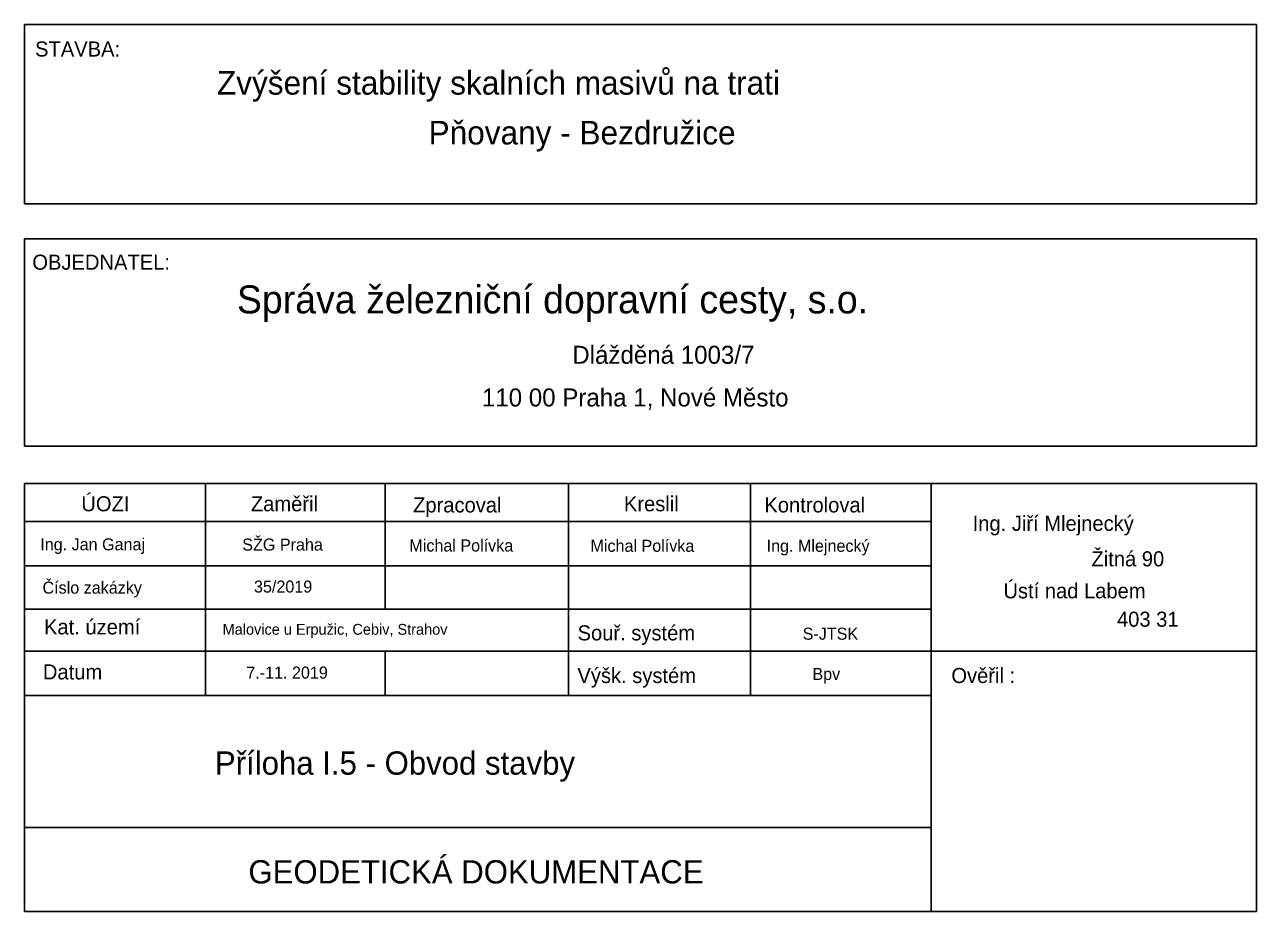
# Model space of a CAD drawing. Extents: x -879530 to -879371, y -1019242 to -1019127.
import ezdxf

# ---------------------------------------------------------------- set-up
doc = ezdxf.new("R2010")
doc.units = 0
doc.layers.add('LEGENDA', color=7, linetype='Continuous')
doc.layers.add('tabulka', color=7, linetype='Continuous')

msp = doc.modelspace()

# ---------------------------------------------------------------- linework, layer by layer
at = {"layer": 'tabulka'}
for p, q in [((-879530.09, -1019186.45), (-879371.44, -1019186.45)), ((-879506.8, -1019186.45), (-879506.8, -1019213.77)), ((-879483.66, -1019186.45), (-879483.66, -1019202.65)), ((-879460.06, -1019186.45), (-879460.06, -1019213.77)), ((-879436.61, -1019186.45), (-879436.61, -1019213.77)), ((-879413.31, -1019241.58), (-879413.31, -1019186.45)), ((-879530.09, -1019191.36), (-879413.31, -1019191.36)), ((-879530.09, -1019197.07), (-879413.31, -1019197.07)), ((-879530.09, -1019202.65), (-879413.31, -1019202.65)), ((-879530.09, -1019208.07), (-879371.44, -1019208.07)), ((-879483.66, -1019208.07), (-879483.66, -1019213.77)), ((-879530.09, -1019213.77), (-879413.31, -1019213.77)), ((-879530.09, -1019230.76), (-879413.31, -1019230.76))]:
    msp.add_line(p, q, dxfattribs=at)
for points in [[(-879530.09, -1019127.36), (-879371.44, -1019127.36), (-879371.44, -1019150.43), (-879530.09, -1019150.43)], [(-879530.09, -1019154.95), (-879371.44, -1019154.95), (-879371.44, -1019181.64), (-879530.09, -1019181.64)]]:
    msp.add_lwpolyline(points, close=True, dxfattribs=at)
msp.add_lwpolyline([(-879371.44, -1019186.45), (-879371.44, -1019241.58), (-879530.09, -1019241.58), (-879530.09, -1019186.45)], dxfattribs=at)

# ---------------------------------------------------------------- texts
at = {"layer": 'LEGENDA'}
for s, p in [('Zvýšení stability skalních masivů na trati', (-879505.32, -1019136.38)), ('Pňovany - Bezdružice', (-879478.06, -1019142.8))]:
    msp.add_text(s, height=3.04, dxfattribs=at).set_placement(p)
at = {"layer": 'tabulka'}
for s, height, p in [('STAVBA:', 1.94, (-879528.75, -1019131.47)), ('OBJEDNATEL:', 1.94, (-879529.1, -1019158.93)), ('Správa železniční dopravní cesty, s.o.', 3.61, (-879502.75, -1019164.56)), ('Dlážděná 1003/7', 2.32, (-879459.55, -1019171.05)), ('110 00 Praha 1, Nové Město', 2.32, (-879471.19, -1019176.55)), ('ÚOZI', 1.94, (-879522.79, -1019190.05)), ('Zaměřil', 1.94, (-879500.95, -1019190.05)), ('Zpracoval', 1.94, (-879480.06, -1019190.2)), ('Kreslil', 1.94, (-879452.9, -1019190.05)), ('Kontroloval', 1.94, (-879434.81, -1019190.2)), ('Ing. Jiří Mlejnecký', 1.94, (-879407.98, -1019192.57)), ('Ing. Jan Ganaj', 1.552, (-879528.08, -1019195.08)), ('SŽG Praha', 1.552, (-879502.06, -1019195.11)), ('Michal Polívka', 1.552, (-879480.54, -1019195.23)), ('Michal Polívka', 1.552, (-879457.21, -1019195.27)), ('Ing. Mlejnecký', 1.552, (-879434.52, -1019195.27)), ('Žitná 90', 1.94, (-879392.68, -1019197.14)), ('Číslo zakázky', 1.552, (-879527.79, -1019200.66)), ('35/2019', 1.552, (-879500.55, -1019200.52)), ('Ústí nad Labem', 1.94, (-879404.02, -1019201.26)), ('403 31', 1.94, (-879389.39, -1019204.92)), ('Kat. území', 1.94, (-879527.6, -1019205.91)), ('Malovice u Erpužic, Cebiv, Strahov', 1.3968, (-879504.59, -1019205.95)), ('Souř. systém', 1.94, (-879458.87, -1019206.68)), ('S-JTSK', 1.552, (-879429.88, -1019206.59)), ('Datum', 1.94, (-879527.74, -1019211.71)), ('7.-11. 2019', 1.552, (-879501.54, -1019211.6)), ('Výšk. systém', 1.94, (-879458.89, -1019212.17)), ('Bpv', 1.552, (-879428.62, -1019211.78)), ('Ověřil :', 1.94, (-879410.72, -1019212.17)), ('Příloha I.5 - Obvod stavby', 3, (-879505.58, -1019223.98)), ('GEODETICKÁ DOKUMENTACE ', 3, (-879501.27, -1019237.99))]:
    msp.add_text(s, height=height, dxfattribs=at).set_placement(p)

doc.saveas('drawing.dxf')
